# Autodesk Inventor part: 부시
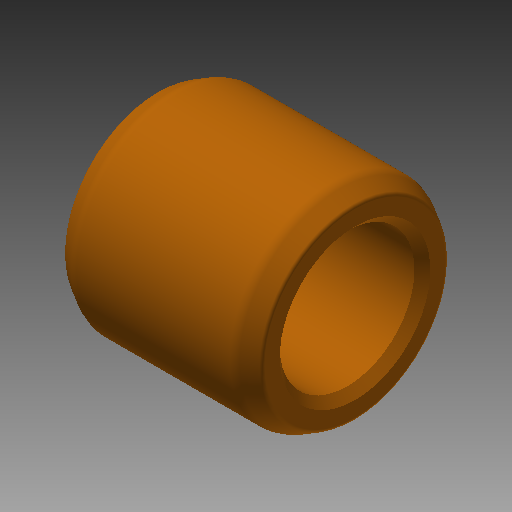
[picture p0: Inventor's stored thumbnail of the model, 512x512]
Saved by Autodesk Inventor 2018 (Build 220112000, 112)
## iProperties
Created: 2018-11
Part Number: 부시
Material: 강철, 연강
Document SubType Name: Modeling
Designer: mduedu
Density: 1 g/cm^3
Appearance: 주황색
Author: mduedu
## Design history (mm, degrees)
sketch "스케치1"
  geometry: C1 r 8.5 at (0, 0); C2 r 13 at (0, 0); 1 further point
  constraints: 2 centre point, 2 coincident
  dimensions: "d0" = 17 diameter of C1; "d1" = 26 diameter of C2
extrude "돌출1" new body sketch "스케치1" distance "d2" = 25; taper "d3" = 0 deg
chamfer "모따기4" distance "d14" = 1; stored, may be unused: second distance "d15" = 2, angle "d16" = 15 deg
chamfer "모따기5" distance "d17" = 2.3; stored, may be unused: second distance "d18" = 2, angle "d19" = 30 deg
chamfer "모따기6" distance "d20" = 2.3; stored, may be unused: second distance "d21" = 2, angle "d22" = 30 deg
fillet "모깎기2" dims "d23" = 2, "d24" = 0.5
fillet "모깎기3" dims "d25" = 2, "d26" = 0.5
node "솔리드1"
